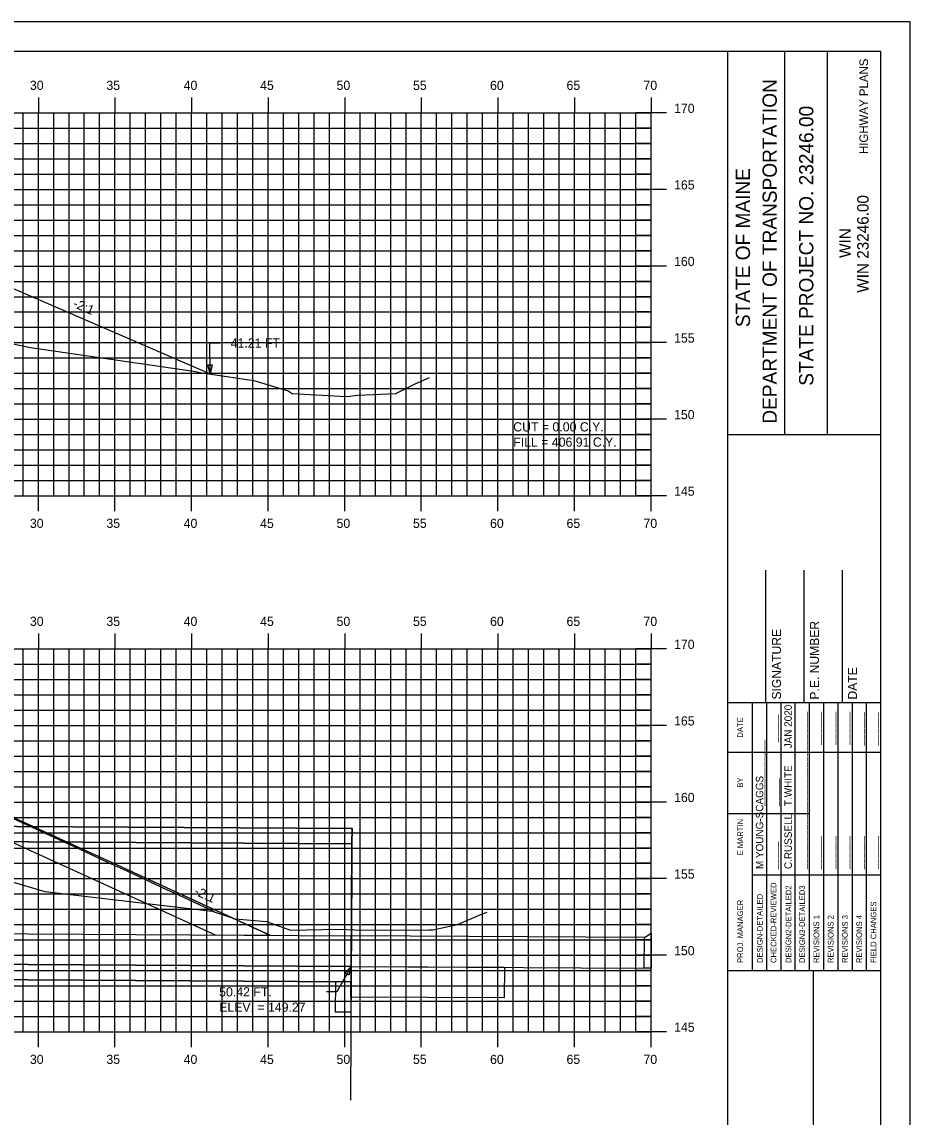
# Model space of a CAD drawing. Extents: x 1141202 to 1141372, y 608981 to 609091.
# Drawn here: x 1141314.4 to 1141372.4, y 609019.8 to 609091.3 of the extents above; entities that cross this region are included whole.
import ezdxf

# ---------------------------------------------------------------- set-up
doc = ezdxf.new("R2010")
doc.units = 0
for name, color, linetype in [('ANNOTATION', 7, 'Continuous'), ('BORDER', 7, 'Continuous'), ('D_Drainage_Culvert', 7, 'Continuous'), ('D_Roadway_SlopeLines', 7, 'Continuous'), ('D_Roadway_SubGrade', 7, 'Continuous'), ('D_Text_Standard', 7, 'Continuous'), ('H_V ANNOTATION', 7, 'Continuous'), ('HIGHWAY_TITLE', 7, 'Continuous'), ('JUNK', 7, 'Continuous'), ('MAJOR', 7, 'Continuous'), ('MINOR', 7, 'Continuous'), ('PATTERNING', 7, 'Continuous'), ('PLOT BOUNDARY', 7, 'Continuous'), ('S_Roadway_Centerline', 7, 'Continuous')]:
    doc.layers.add(name, color=color, linetype=linetype)

msp = doc.modelspace()

# ---------------------------------------------------------------- linework, layer by layer
for points in [[(1141252.234, 609072.746), (1141257.978, 609074.853), (1141260.705, 609075.853), (1141267.513, 609078.349), (1141267.514, 609078.349), (1141274.514, 609078.629), (1141285.514, 609078.849), (1141296.514, 609078.629), (1141303.514, 609078.349), (1141309.224, 609075.875), (1141311.532, 609074.875), (1141326.721, 609068.292)], [(1141305.345, 609043.216), (1141305.376, 609043.202), (1141305.396, 609043.193), (1141306.145, 609042.845), (1141307.41, 609042.26), (1141308.468, 609041.769), (1141309.026, 609041.511), (1141310.304, 609040.919), (1141310.791, 609040.694), (1141311.659, 609040.291), (1141312.468, 609039.917), (1141313.034, 609039.654), (1141313.113, 609039.618), (1141315.076, 609038.709), (1141315.434, 609038.543), (1141317.138, 609037.754), (1141317.755, 609037.468), (1141318.557, 609037.097), (1141320.075, 609036.394), (1141321.235, 609035.857), (1141322.395, 609035.32), (1141323.928, 609034.61), (1141324.715, 609034.246), (1141326.998, 609033.189)]]:
    msp.add_lwpolyline(points)
at = {"layer": 'BORDER'}
for p, q in [((1141360.514, 608984.335), (1141360.514, 609089.335)), ((1141364.243, 609064.332), (1141364.243, 609089.332)), ((1141367.038, 609064.332), (1141367.038, 609089.332)), ((1141360.515, 609064.329), (1141370.514, 609064.329)), ((1141363.014, 609046.838), (1141363.014, 609055.485)), ((1141365.514, 609046.838), (1141365.514, 609055.485)), ((1141368.014, 609046.838), (1141368.014, 609055.485)), ((1141360.514, 609046.838), (1141370.514, 609046.838)), ((1141360.514, 609029.338), (1141370.514, 609029.338)), ((1141366.105, 608994.338), (1141366.105, 609029.338))]:
    msp.add_line(p, q, dxfattribs=at)
msp.add_lwpolyline([(1141210.514, 608984.335), (1141370.514, 608984.335), (1141370.514, 609089.335), (1141210.514, 609089.335)], close=True, dxfattribs=at)
for points in [[(1141362.129, 609043.588), (1141362.129, 609046.838)], [(1141363.062, 609029.341), (1141363.062, 609046.838)], [(1141363.993, 609046.838), (1141363.993, 609029.341)], [(1141364.925, 609029.341), (1141364.925, 609046.838)], [(1141365.857, 609029.341), (1141365.857, 609046.838)], [(1141366.789, 609029.341), (1141366.789, 609046.838)], [(1141367.72, 609029.341), (1141367.72, 609046.838)], [(1141368.652, 609029.341), (1141368.652, 609046.838)], [(1141369.584, 609029.341), (1141369.584, 609046.838)], [(1141362.13, 609029.341), (1141362.13, 609046.132)], [(1141360.514, 609043.588), (1141370.514, 609043.588)], [(1141360.514, 609039.588), (1141362.13, 609039.588)], [(1141362.129, 609039.588), (1141365.856, 609039.588)], [(1141362.129, 609035.588), (1141370.514, 609035.588)]]:
    msp.add_lwpolyline(points, dxfattribs=at)
at = {"layer": 'D_Drainage_Culvert'}
for points in [[(1141240.936, 609030.185), (1141240.985, 609038.185), (1141240.991, 609039.185), (1141335.989, 609038.605), (1141335.983, 609037.605), (1141335.934, 609029.606), (1141335.916, 609026.606), (1141334.916, 609026.612), (1141334.928, 609028.612), (1141335.928, 609028.606), (1141240.93, 609029.185), (1141240.918, 609027.185), (1141241.918, 609027.179), (1141241.93, 609029.179)], [(1141240.934, 609030.185), (1141335.934, 609029.606), (1141335.983, 609037.605), (1141240.985, 609038.185), (1141240.936, 609030.185)]]:
    msp.add_lwpolyline(points, dxfattribs=at)
at = {"layer": 'D_Roadway_SlopeLines'}
msp.add_lwpolyline([(1141311.532, 609074.875), (1141326.721, 609068.292)], dxfattribs=at)
at = {"layer": 'D_Roadway_SubGrade'}
msp.add_lwpolyline([(1141304.985, 609043.383), (1141320.188, 609036.444), (1141330.629, 609031.638)], dxfattribs=at)
at = {"layer": 'D_Text_Standard'}
for points in [[(1141326.721, 609068.292), (1141326.71, 609070.31), (1141327.39, 609070.31)], [(1141335.934, 609029.606), (1141335.001, 609027.943), (1141334.321, 609027.943)]]:
    msp.add_lwpolyline(points, dxfattribs=at)
for points in [[(1141326.721, 609068.292), (1141326.572, 609068.874), (1141326.863, 609068.875)], [(1141335.934, 609029.606), (1141335.776, 609029.027), (1141335.522, 609029.169)]]:
    msp.add_lwpolyline(points, close=True, dxfattribs=at)
at = {"layer": 'JUNK'}
msp.add_lwpolyline([(1141335.97, 609035.522), (1141335.934, 609029.606), (1141335.881, 609020.865)], dxfattribs=at)
at = {"layer": 'MAJOR'}
for p, q in [((1141315.514, 609086.337), (1141315.514, 609085.335)), ((1141320.514, 609086.337), (1141320.514, 609085.335)), ((1141325.514, 609086.337), (1141325.514, 609085.335)), ((1141330.514, 609086.337), (1141330.514, 609085.335)), ((1141335.514, 609086.337), (1141335.514, 609085.335)), ((1141340.514, 609086.337), (1141340.514, 609085.335)), ((1141345.514, 609086.337), (1141345.514, 609085.335)), ((1141350.514, 609086.337), (1141350.514, 609085.335)), ((1141355.514, 609086.337), (1141355.514, 609085.335)), ((1141215.514, 609085.335), (1141355.514, 609085.335)), ((1141215.514, 609085.335), (1141355.514, 609085.335)), ((1141315.514, 609060.335), (1141315.514, 609085.335)), ((1141320.514, 609060.335), (1141320.514, 609085.335)), ((1141325.514, 609060.335), (1141325.514, 609085.335)), ((1141330.514, 609060.335), (1141330.514, 609085.335)), ((1141335.514, 609060.335), (1141335.514, 609085.335)), ((1141340.514, 609060.335), (1141340.514, 609085.335)), ((1141345.514, 609060.335), (1141345.514, 609085.335)), ((1141350.514, 609060.335), (1141350.514, 609085.335)), ((1141356.516, 609085.335), (1141354.512, 609085.335)), ((1141355.514, 609060.335), (1141355.514, 609085.335)), ((1141355.514, 609060.335), (1141355.514, 609085.335)), ((1141215.514, 609080.335), (1141355.514, 609080.335)), ((1141356.516, 609080.335), (1141354.512, 609080.335)), ((1141215.514, 609075.335), (1141355.514, 609075.335)), ((1141356.516, 609075.335), (1141354.512, 609075.335)), ((1141215.514, 609070.335), (1141355.514, 609070.335)), ((1141356.516, 609070.335), (1141354.512, 609070.335)), ((1141215.514, 609065.335), (1141355.514, 609065.335)), ((1141356.516, 609065.335), (1141354.512, 609065.335)), ((1141215.514, 609060.335), (1141355.514, 609060.335)), ((1141215.514, 609060.335), (1141355.514, 609060.335)), ((1141315.514, 609059.333), (1141315.514, 609060.335)), ((1141320.514, 609059.333), (1141320.514, 609060.335)), ((1141325.514, 609059.333), (1141325.514, 609060.335)), ((1141330.514, 609059.333), (1141330.514, 609060.335)), ((1141335.514, 609059.333), (1141335.514, 609060.335)), ((1141340.514, 609059.333), (1141340.514, 609060.335)), ((1141345.514, 609059.333), (1141345.514, 609060.335)), ((1141350.514, 609059.333), (1141350.514, 609060.335)), ((1141356.516, 609060.335), (1141354.512, 609060.335)), ((1141355.514, 609059.333), (1141355.514, 609060.335)), ((1141315.514, 609051.337), (1141315.514, 609050.335)), ((1141320.514, 609051.337), (1141320.514, 609050.335)), ((1141325.514, 609051.337), (1141325.514, 609050.335)), ((1141330.514, 609051.337), (1141330.514, 609050.335)), ((1141335.514, 609051.337), (1141335.514, 609050.335)), ((1141340.514, 609051.337), (1141340.514, 609050.335)), ((1141345.514, 609051.337), (1141345.514, 609050.335)), ((1141350.514, 609051.337), (1141350.514, 609050.335)), ((1141355.514, 609051.337), (1141355.514, 609050.335)), ((1141215.514, 609050.335), (1141355.514, 609050.335)), ((1141215.514, 609050.335), (1141355.514, 609050.335)), ((1141315.514, 609025.335), (1141315.514, 609050.335)), ((1141320.514, 609025.335), (1141320.514, 609050.335)), ((1141325.514, 609025.335), (1141325.514, 609050.335)), ((1141330.514, 609025.335), (1141330.514, 609050.335)), ((1141335.514, 609025.335), (1141335.514, 609050.335)), ((1141340.514, 609025.335), (1141340.514, 609050.335)), ((1141345.514, 609025.335), (1141345.514, 609050.335)), ((1141350.514, 609025.335), (1141350.514, 609050.335)), ((1141356.516, 609050.335), (1141354.512, 609050.335)), ((1141355.514, 609025.335), (1141355.514, 609050.335)), ((1141355.514, 609025.335), (1141355.514, 609050.335)), ((1141215.514, 609045.335), (1141355.514, 609045.335)), ((1141356.516, 609045.335), (1141354.512, 609045.335)), ((1141215.514, 609040.335), (1141355.514, 609040.335)), ((1141356.516, 609040.335), (1141354.512, 609040.335)), ((1141215.514, 609035.335), (1141355.514, 609035.335)), ((1141356.516, 609035.335), (1141354.512, 609035.335)), ((1141215.514, 609030.335), (1141355.514, 609030.335)), ((1141356.516, 609030.335), (1141354.512, 609030.335)), ((1141215.514, 609025.335), (1141355.514, 609025.335)), ((1141215.514, 609025.335), (1141355.514, 609025.335)), ((1141315.514, 609024.333), (1141315.514, 609025.335)), ((1141320.514, 609024.333), (1141320.514, 609025.335)), ((1141325.514, 609024.333), (1141325.514, 609025.335)), ((1141330.514, 609024.333), (1141330.514, 609025.335)), ((1141335.514, 609024.333), (1141335.514, 609025.335)), ((1141340.514, 609024.333), (1141340.514, 609025.335)), ((1141345.514, 609024.333), (1141345.514, 609025.335)), ((1141350.514, 609024.333), (1141350.514, 609025.335)), ((1141356.516, 609025.335), (1141354.512, 609025.335)), ((1141355.514, 609024.333), (1141355.514, 609025.335))]:
    msp.add_line(p, q, dxfattribs=at)
at = {"layer": 'MINOR'}
for p, q in [((1141314.514, 609060.335), (1141314.514, 609085.335)), ((1141316.514, 609060.335), (1141316.514, 609085.335)), ((1141317.514, 609060.335), (1141317.514, 609085.335)), ((1141318.514, 609060.335), (1141318.514, 609085.335)), ((1141319.514, 609060.335), (1141319.514, 609085.335)), ((1141321.514, 609060.335), (1141321.514, 609085.335)), ((1141322.514, 609060.335), (1141322.514, 609085.335)), ((1141323.514, 609060.335), (1141323.514, 609085.335)), ((1141324.514, 609060.335), (1141324.514, 609085.335)), ((1141326.514, 609060.335), (1141326.514, 609085.335)), ((1141327.514, 609060.335), (1141327.514, 609085.335)), ((1141328.514, 609060.335), (1141328.514, 609085.335)), ((1141329.514, 609060.335), (1141329.514, 609085.335)), ((1141331.514, 609060.335), (1141331.514, 609085.335)), ((1141332.514, 609060.335), (1141332.514, 609085.335)), ((1141333.514, 609060.335), (1141333.514, 609085.335)), ((1141334.514, 609060.335), (1141334.514, 609085.335)), ((1141336.514, 609060.335), (1141336.514, 609085.335)), ((1141337.514, 609060.335), (1141337.514, 609085.335)), ((1141338.514, 609060.335), (1141338.514, 609085.335)), ((1141339.514, 609060.335), (1141339.514, 609085.335)), ((1141341.514, 609060.335), (1141341.514, 609085.335)), ((1141342.514, 609060.335), (1141342.514, 609085.335)), ((1141343.514, 609060.335), (1141343.514, 609085.335)), ((1141344.514, 609060.335), (1141344.514, 609085.335)), ((1141346.514, 609060.335), (1141346.514, 609085.335)), ((1141347.514, 609060.335), (1141347.514, 609085.335)), ((1141348.514, 609060.335), (1141348.514, 609085.335)), ((1141349.514, 609060.335), (1141349.514, 609085.335)), ((1141351.514, 609060.335), (1141351.514, 609085.335)), ((1141352.514, 609060.335), (1141352.514, 609085.335)), ((1141353.514, 609060.335), (1141353.514, 609085.335)), ((1141354.514, 609060.335), (1141354.514, 609085.335)), ((1141215.514, 609084.335), (1141355.514, 609084.335)), ((1141355.514, 609084.335), (1141354.512, 609084.335)), ((1141215.514, 609083.335), (1141355.514, 609083.335)), ((1141355.514, 609083.335), (1141354.512, 609083.335)), ((1141215.514, 609082.335), (1141355.514, 609082.335)), ((1141355.514, 609082.335), (1141354.512, 609082.335)), ((1141215.514, 609081.335), (1141355.514, 609081.335)), ((1141355.514, 609081.335), (1141354.512, 609081.335)), ((1141215.514, 609079.335), (1141355.514, 609079.335)), ((1141355.514, 609079.335), (1141354.512, 609079.335)), ((1141215.514, 609078.335), (1141355.514, 609078.335)), ((1141355.514, 609078.335), (1141354.512, 609078.335)), ((1141215.514, 609077.335), (1141355.514, 609077.335)), ((1141355.514, 609077.335), (1141354.512, 609077.335)), ((1141215.514, 609076.335), (1141355.514, 609076.335)), ((1141355.514, 609076.335), (1141354.512, 609076.335)), ((1141215.514, 609074.335), (1141355.514, 609074.335)), ((1141355.514, 609074.335), (1141354.512, 609074.335)), ((1141215.514, 609073.335), (1141355.514, 609073.335)), ((1141355.514, 609073.335), (1141354.512, 609073.335)), ((1141215.514, 609072.335), (1141355.514, 609072.335)), ((1141355.514, 609072.335), (1141354.512, 609072.335)), ((1141215.514, 609071.335), (1141355.514, 609071.335)), ((1141355.514, 609071.335), (1141354.512, 609071.335)), ((1141215.514, 609069.335), (1141355.514, 609069.335)), ((1141355.514, 609069.335), (1141354.512, 609069.335)), ((1141215.514, 609068.335), (1141355.514, 609068.335)), ((1141355.514, 609068.335), (1141354.512, 609068.335)), ((1141215.514, 609067.335), (1141355.514, 609067.335)), ((1141355.514, 609067.335), (1141354.512, 609067.335)), ((1141215.514, 609066.335), (1141355.514, 609066.335)), ((1141355.514, 609066.335), (1141354.512, 609066.335)), ((1141215.514, 609064.335), (1141355.514, 609064.335)), ((1141355.514, 609064.335), (1141354.512, 609064.335)), ((1141215.514, 609063.335), (1141355.514, 609063.335)), ((1141355.514, 609063.335), (1141354.512, 609063.335)), ((1141215.514, 609062.335), (1141355.514, 609062.335)), ((1141355.514, 609062.335), (1141354.512, 609062.335)), ((1141215.514, 609061.335), (1141355.514, 609061.335)), ((1141355.514, 609061.335), (1141354.512, 609061.335)), ((1141314.514, 609025.335), (1141314.514, 609050.335)), ((1141316.514, 609025.335), (1141316.514, 609050.335)), ((1141317.514, 609025.335), (1141317.514, 609050.335)), ((1141318.514, 609025.335), (1141318.514, 609050.335)), ((1141319.514, 609025.335), (1141319.514, 609050.335)), ((1141321.514, 609025.335), (1141321.514, 609050.335)), ((1141322.514, 609025.335), (1141322.514, 609050.335)), ((1141323.514, 609025.335), (1141323.514, 609050.335)), ((1141324.514, 609025.335), (1141324.514, 609050.335)), ((1141326.514, 609025.335), (1141326.514, 609050.335)), ((1141327.514, 609025.335), (1141327.514, 609050.335)), ((1141328.514, 609025.335), (1141328.514, 609050.335)), ((1141329.514, 609025.335), (1141329.514, 609050.335)), ((1141331.514, 609025.335), (1141331.514, 609050.335)), ((1141332.514, 609025.335), (1141332.514, 609050.335)), ((1141333.514, 609025.335), (1141333.514, 609050.335)), ((1141334.514, 609025.335), (1141334.514, 609050.335)), ((1141336.514, 609025.335), (1141336.514, 609050.335)), ((1141337.514, 609025.335), (1141337.514, 609050.335)), ((1141338.514, 609025.335), (1141338.514, 609050.335)), ((1141339.514, 609025.335), (1141339.514, 609050.335)), ((1141341.514, 609025.335), (1141341.514, 609050.335)), ((1141342.514, 609025.335), (1141342.514, 609050.335)), ((1141343.514, 609025.335), (1141343.514, 609050.335)), ((1141344.514, 609025.335), (1141344.514, 609050.335)), ((1141346.514, 609025.335), (1141346.514, 609050.335)), ((1141347.514, 609025.335), (1141347.514, 609050.335)), ((1141348.514, 609025.335), (1141348.514, 609050.335)), ((1141349.514, 609025.335), (1141349.514, 609050.335)), ((1141351.514, 609025.335), (1141351.514, 609050.335)), ((1141352.514, 609025.335), (1141352.514, 609050.335)), ((1141353.514, 609025.335), (1141353.514, 609050.335)), ((1141354.514, 609025.335), (1141354.514, 609050.335)), ((1141215.514, 609049.335), (1141355.514, 609049.335)), ((1141355.514, 609049.335), (1141354.512, 609049.335)), ((1141215.514, 609048.335), (1141355.514, 609048.335)), ((1141355.514, 609048.335), (1141354.512, 609048.335)), ((1141215.514, 609047.335), (1141355.514, 609047.335)), ((1141355.514, 609047.335), (1141354.512, 609047.335)), ((1141215.514, 609046.335), (1141355.514, 609046.335)), ((1141355.514, 609046.335), (1141354.512, 609046.335)), ((1141215.514, 609044.335), (1141355.514, 609044.335)), ((1141355.514, 609044.335), (1141354.512, 609044.335)), ((1141215.514, 609043.335), (1141355.514, 609043.335)), ((1141355.514, 609043.335), (1141354.512, 609043.335)), ((1141215.514, 609042.335), (1141355.514, 609042.335)), ((1141355.514, 609042.335), (1141354.512, 609042.335)), ((1141215.514, 609041.335), (1141355.514, 609041.335)), ((1141355.514, 609041.335), (1141354.512, 609041.335)), ((1141215.514, 609039.335), (1141355.514, 609039.335)), ((1141355.514, 609039.335), (1141354.512, 609039.335)), ((1141215.514, 609038.335), (1141355.514, 609038.335)), ((1141355.514, 609038.335), (1141354.512, 609038.335)), ((1141215.514, 609037.335), (1141355.514, 609037.335)), ((1141355.514, 609037.335), (1141354.512, 609037.335)), ((1141215.514, 609036.335), (1141355.514, 609036.335)), ((1141355.514, 609036.335), (1141354.512, 609036.335)), ((1141215.514, 609034.335), (1141355.514, 609034.335)), ((1141355.514, 609034.335), (1141354.512, 609034.335)), ((1141215.514, 609033.335), (1141355.514, 609033.335)), ((1141355.514, 609033.335), (1141354.512, 609033.335)), ((1141215.514, 609032.335), (1141355.514, 609032.335)), ((1141355.514, 609032.335), (1141354.512, 609032.335)), ((1141215.514, 609031.335), (1141355.514, 609031.335)), ((1141355.514, 609031.335), (1141354.512, 609031.335)), ((1141215.514, 609029.335), (1141355.514, 609029.335)), ((1141355.514, 609029.335), (1141354.512, 609029.335)), ((1141215.514, 609028.335), (1141355.514, 609028.335)), ((1141355.514, 609028.335), (1141354.512, 609028.335)), ((1141215.514, 609027.335), (1141355.514, 609027.335)), ((1141355.514, 609027.335), (1141354.512, 609027.335)), ((1141215.514, 609026.335), (1141355.514, 609026.335)), ((1141355.514, 609026.335), (1141354.512, 609026.335))]:
    msp.add_line(p, q, dxfattribs=at)
at = {"layer": 'PATTERNING'}
for points in [[(1141330.629, 609031.638), (1141322.005, 609035.607), (1141313.354, 609039.563), (1141312.731, 609038.198), (1141327.056, 609031.66)], [(1141240.991, 609039.185), (1141240.985, 609038.185), (1141335.983, 609037.605), (1141335.989, 609038.605)], [(1141335.946, 609031.606), (1141335.934, 609029.606), (1141240.934, 609030.185), (1141240.946, 609032.185)], [(1141355.084, 609031.489), (1141355.514, 609031.772), (1141355.514, 609029.489), (1141355.072, 609029.489)], [(1141335.934, 609029.606), (1141350.934, 609029.514), (1141355.072, 609029.489), (1141355.084, 609031.489), (1141335.946, 609031.606)], [(1141335.928, 609028.606), (1141335.934, 609029.606), (1141240.934, 609030.185), (1141240.93, 609029.185)], [(1141335.934, 609029.606), (1141345.934, 609029.545), (1141345.922, 609027.545), (1141335.922, 609027.606)], [(1141334.928, 609028.612), (1141335.928, 609028.606), (1141335.916, 609026.606), (1141334.916, 609026.612)]]:
    msp.add_lwpolyline(points, close=True, dxfattribs=at)
at = {"layer": 'PLOT BOUNDARY'}
msp.add_lwpolyline([(1141202.421, 608981.276), (1141372.421, 608981.276), (1141372.421, 609091.276), (1141202.421, 609091.276)], close=True, dxfattribs=at)
at = {"layer": 'S_Roadway_Centerline'}
for points in [[(1141313.651, 609070.289), (1141315, 609070.011), (1141325.791, 609068.449), (1141326.168, 609068.363), (1141326.634, 609068.306), (1141329.587, 609067.858), (1141331.824, 609067.177), (1141332.079, 609067.009), (1141335.215, 609066.844), (1141335.701, 609066.825), (1141336.368, 609066.91), (1141338.858, 609067.007), (1141340.111, 609067.634), (1141341.058, 609068.055)], [(1141312.023, 609035.648), (1141315.938, 609034.498), (1141326.854, 609033.219), (1141328.357, 609032.702), (1141330.405, 609032.541), (1141331.965, 609031.961), (1141335.134, 609032.045), (1141336.733, 609031.975), (1141341.027, 609031.998), (1141341.272, 609031.998), (1141342.874, 609032.341), (1141344.546, 609033.058), (1141344.803, 609033.155)]]:
    msp.add_lwpolyline(points, dxfattribs=at)

# ---------------------------------------------------------------- texts
at = {"layer": 'ANNOTATION'}
for rotation, p in [(336.57137, (1141317.73, 609072.678)), (335.16173, (1141325.644, 609034.318))]:
    msp.add_text('-2:1', height=0.6, rotation=rotation, dxfattribs=at).set_placement(p)
at = {"layer": 'BORDER'}
for s, height, p in [('DEPARTMENT OF TRANSPORTATION', 0.93176, (1141363.721, 609065.041)), ('STATE PROJECT NO. 23246.00', 0.93176, (1141366.106, 609067.517)), ('STATE OF MAINE', 0.93176, (1141361.97, 609071.347)), ('WIN 23246.00', 0.74527, (1141369.71, 609073.596)), ('WIN', 0.7453, (1141368.551, 609075.865)), ('P.E. NUMBER', 0.59055, (1141366.475, 609047.03)), ('SIGNATURE', 0.5906, (1141363.995, 609047.03)), ('DATE', 0.5906, (1141368.955, 609047.03)), ('_____', 0.4845, (1141363.732, 609044.243)), ('JAN 2020', 0.4845, (1141364.701, 609043.843)), ('______', 0.4845, (1141365.595, 609044.063)), ('______', 0.4845, (1141366.527, 609044.065)), ('______', 0.4845, (1141367.458, 609044.067)), ('______', 0.4845, (1141368.39, 609044.067)), ('______', 0.4845, (1141369.322, 609044.036)), ('______', 0.4845, (1141370.253, 609044.036)), ('DATE', 0.3714, (1141361.519, 609044.544)), ('____________', 0.48455, (1141362.837, 609040.073)), ('____________', 0.48455, (1141365.595, 609040.073)), ('T.WHITE', 0.4845, (1141364.701, 609040.073)), ('BY', 0.3714, (1141361.519, 609041.273)), ('M YOUNG-SCAGGS', 0.48455, (1141362.837, 609035.961)), ('_____', 0.4845, (1141363.769, 609040.073)), ('____________', 0.48455, (1141365.595, 609035.961)), ('E MARTIN', 0.3727, (1141361.519, 609036.855)), ('C.RUSSELL', 0.4845, (1141364.701, 609035.961)), ('______', 0.4845, (1141366.527, 609035.961)), ('______', 0.4845, (1141367.458, 609035.961)), ('______', 0.4845, (1141368.39, 609035.961)), ('______', 0.4845, (1141369.322, 609035.961)), ('______', 0.4845, (1141370.253, 609035.961)), ('_____', 0.4845, (1141363.732, 609035.961)), ('CHECKED-REVIEWED', 0.37275, (1141363.695, 609029.826)), ('DESIGN2-DETAILED2', 0.37275, (1141364.664, 609029.826)), ('DESIGN3-DETAILED3', 0.37275, (1141365.559, 609029.826)), ('PROJ. MANAGER', 0.37275, (1141361.519, 609029.826)), ('DESIGN-DETAILED', 0.37275, (1141362.801, 609029.826)), ('FIELD CHANGES', 0.37275, (1141370.217, 609029.826)), ('REVISIONS 1', 0.37275, (1141366.49, 609029.826)), ('REVISIONS 2', 0.37275, (1141367.422, 609029.826)), ('REVISIONS 3', 0.37275, (1141368.354, 609029.826)), ('REVISIONS 4', 0.37275, (1141369.285, 609029.826))]:
    msp.add_text(s, height=height, rotation=90, dxfattribs=at).set_placement(p)
at = {"layer": 'D_Text_Standard'}
for s, p in [('41.21 FT', (1141328.07, 609070.01)), ('CUT = 0.00 C.Y.', (1141346.514, 609064.535)), ('FILL = 406.91 C.Y.', (1141346.514, 609063.539)), ('50.42 FT.', (1141327.317, 609027.643)), ('ELEV. = 149.27', (1141327.317, 609026.643))]:
    msp.add_text(s, height=0.6, dxfattribs=at).set_placement(p)
at = {"layer": 'H_V ANNOTATION'}
for s, p in [('30', (1141314.963, 609086.835)), ('35', (1141319.955, 609086.835)), ('40', (1141325, 609086.835)), ('45', (1141329.992, 609086.835)), ('50', (1141334.979, 609086.835)), ('55', (1141339.971, 609086.835)), ('60', (1141345, 609086.835)), ('65', (1141349.992, 609086.835)), ('70', (1141355.016, 609086.835)), ('170', (1141357.014, 609085.335)), ('165', (1141357.014, 609080.335)), ('160', (1141357.014, 609075.335)), ('155', (1141357.014, 609070.335)), ('150', (1141357.014, 609065.335)), ('145', (1141357.014, 609060.335)), ('30', (1141314.963, 609058.235)), ('35', (1141319.955, 609058.235)), ('40', (1141325, 609058.235)), ('45', (1141329.992, 609058.235)), ('50', (1141334.979, 609058.235)), ('55', (1141339.971, 609058.235)), ('60', (1141345, 609058.235)), ('65', (1141349.992, 609058.235)), ('70', (1141355.016, 609058.235)), ('30', (1141314.963, 609051.835)), ('35', (1141319.955, 609051.835)), ('40', (1141325, 609051.835)), ('45', (1141329.992, 609051.835)), ('50', (1141334.979, 609051.835)), ('55', (1141339.971, 609051.835)), ('60', (1141345, 609051.835)), ('65', (1141349.992, 609051.835)), ('70', (1141355.016, 609051.835)), ('170', (1141357.014, 609050.335)), ('165', (1141357.014, 609045.335)), ('160', (1141357.014, 609040.335)), ('155', (1141357.014, 609035.335)), ('150', (1141357.014, 609030.335)), ('145', (1141357.014, 609025.335)), ('30', (1141314.963, 609023.235)), ('35', (1141319.955, 609023.235)), ('40', (1141325, 609023.235)), ('45', (1141329.992, 609023.235)), ('50', (1141334.979, 609023.235)), ('55', (1141339.971, 609023.235)), ('60', (1141345, 609023.235)), ('65', (1141349.992, 609023.235)), ('70', (1141355.016, 609023.235))]:
    msp.add_text(s, height=0.6, dxfattribs=at).set_placement(p)
at = {"layer": 'HIGHWAY_TITLE'}
msp.add_text('HIGHWAY PLANS', height=0.55901, rotation=90, dxfattribs=at).set_placement((1141369.673, 609082.65))

doc.saveas('drawing.dxf')
